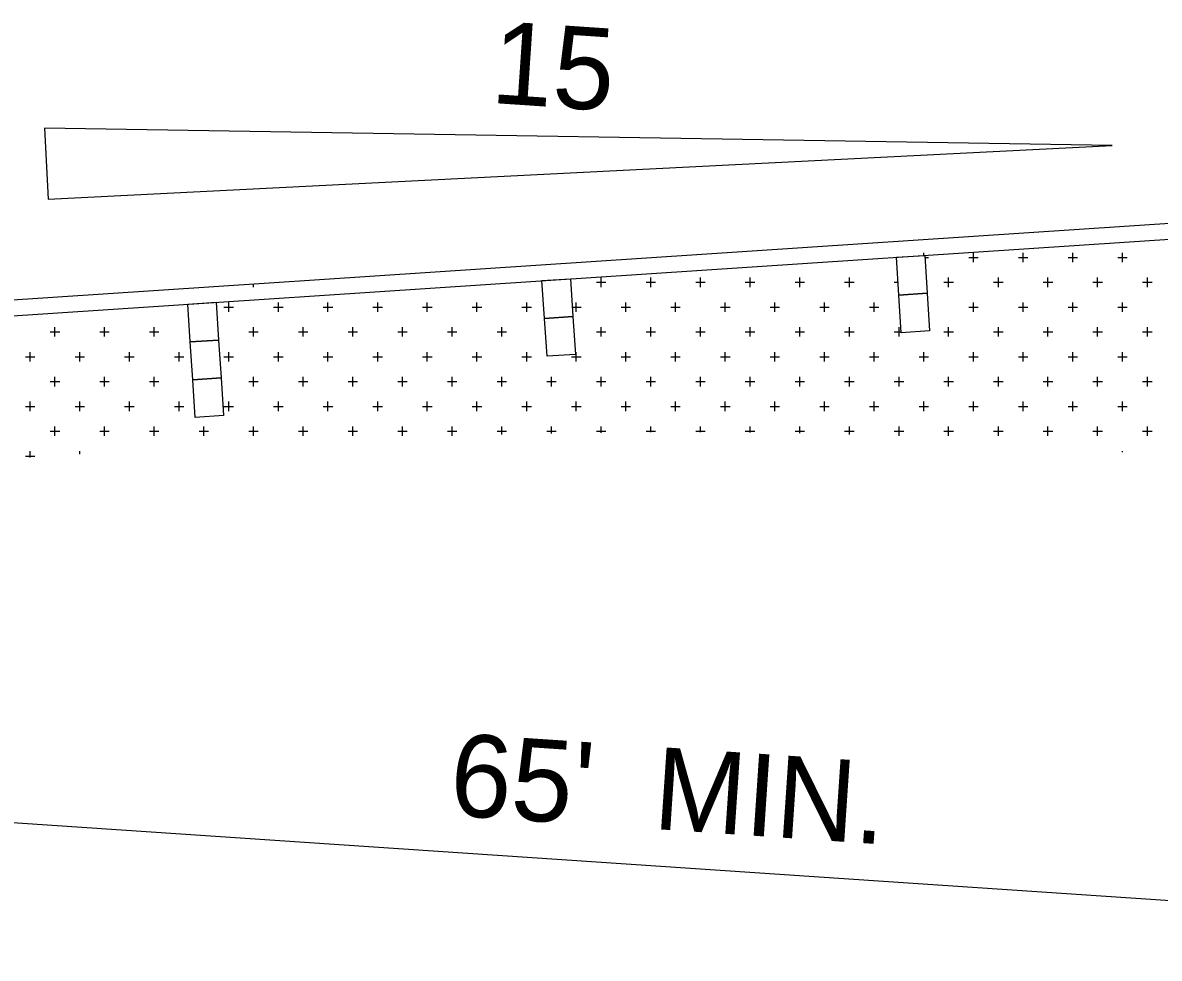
# Model space of a CAD drawing. Extents: x 1312564.5 to 1312581.5, y 1207298.4 to 1207309.4.
# Drawn here: x 1312577.548 to 1312578.654, y 1207304.617 to 1207305.528 of the extents above; entities that cross this region are included whole.
import ezdxf

# ---------------------------------------------------------------- set-up
doc = ezdxf.new("R2010")
doc.units = 0
for name, color, linetype in [('Level 15', 7, 'Continuous'), ('Level 2', 7, 'Continuous'), ('Level 20', 7, 'Continuous'), ('Level 4', 7, 'Continuous')]:
    doc.layers.add(name, color=color, linetype=linetype)

msp = doc.modelspace()

# ---------------------------------------------------------------- linework, layer by layer
at = {"layer": 'Level 15'}
for p, q in [((1312578.6079, 1207305.4083), (1312577.5689, 1207305.4249)), ((1312577.5689, 1207305.4249), (1312577.5724, 1207305.3559)), ((1312577.5724, 1207305.3559), (1312578.6079, 1207305.4083))]:
    msp.add_line(p, q, dxfattribs=at)
msp.add_lwpolyline([(1312576.1506, 1207304.8426), (1312579.498, 1207304.617)], dxfattribs=at)
at = {"layer": 'Level 2'}
for p, q in [((1312579.0887, 1207305.3604), (1312577.009, 1207305.2227)), ((1312577.01, 1207305.2075), (1312579.1015, 1207305.346))]:
    msp.add_line(p, q, dxfattribs=at)
for points in [[(1312578.398, 1207305.2994), (1312578.4256, 1207305.3012), (1312578.428, 1207305.2644), (1312578.4004, 1207305.2626)], [(1312578.0531, 1207305.2766), (1312578.0807, 1207305.2784), (1312578.0831, 1207305.2416), (1312578.0556, 1207305.2398)], [(1312577.7083, 1207305.2537), (1312577.7359, 1207305.2556), (1312577.7383, 1207305.2188), (1312577.7107, 1207305.217)], [(1312578.4004, 1207305.2626), (1312578.428, 1207305.2644), (1312578.4304, 1207305.2277), (1312578.4028, 1207305.2258)], [(1312578.0556, 1207305.2398), (1312578.0831, 1207305.2416), (1312578.0856, 1207305.2048), (1312578.058, 1207305.203)], [(1312577.7107, 1207305.217), (1312577.7383, 1207305.2188), (1312577.7407, 1207305.182), (1312577.7132, 1207305.1802)], [(1312577.7132, 1207305.1802), (1312577.7407, 1207305.182), (1312577.7432, 1207305.1452), (1312577.7156, 1207305.1434)]]:
    msp.add_lwpolyline(points, close=True, dxfattribs=at)
at = {"layer": 'Level 4'}
for p, q in [((1312578.4248, 1207305.3012), (1312578.4248, 1207305.3038)), ((1312578.4257, 1207305.2992), (1312578.4294, 1207305.2992)), ((1312578.4685, 1207305.2992), (1312578.4731, 1207305.2992)), ((1312578.4731, 1207305.2946), (1312578.4731, 1207305.3038)), ((1312578.4731, 1207305.2992), (1312578.4777, 1207305.2992)), ((1312578.5168, 1207305.2992), (1312578.526, 1207305.2992)), ((1312578.5214, 1207305.2946), (1312578.5214, 1207305.3038)), ((1312578.5652, 1207305.2992), (1312578.5744, 1207305.2992)), ((1312578.5698, 1207305.2946), (1312578.5698, 1207305.3038)), ((1312578.6135, 1207305.2992), (1312578.6227, 1207305.2992)), ((1312578.6181, 1207305.2946), (1312578.6181, 1207305.3038)), ((1312578.1107, 1207305.2704), (1312578.1107, 1207305.2796)), ((1312578.159, 1207305.2704), (1312578.159, 1207305.2796)), ((1312578.2073, 1207305.2704), (1312578.2073, 1207305.2796)), ((1312578.2556, 1207305.2704), (1312578.2556, 1207305.2796)), ((1312578.304, 1207305.2704), (1312578.304, 1207305.2796)), ((1312578.3523, 1207305.2704), (1312578.3523, 1207305.2796)), ((1312578.4489, 1207305.2704), (1312578.4489, 1207305.2796)), ((1312578.4973, 1207305.2704), (1312578.4973, 1207305.2796)), ((1312578.5456, 1207305.2704), (1312578.5456, 1207305.2796)), ((1312578.5939, 1207305.2704), (1312578.5939, 1207305.2796)), ((1312578.6423, 1207305.2704), (1312578.6423, 1207305.2796)), ((1312577.7724, 1207305.2704), (1312577.7724, 1207305.2733)), ((1312578.106, 1207305.275), (1312578.1153, 1207305.275)), ((1312578.1544, 1207305.275), (1312578.1636, 1207305.275)), ((1312578.2027, 1207305.275), (1312578.2119, 1207305.275)), ((1312578.251, 1207305.275), (1312578.2602, 1207305.275)), ((1312578.2994, 1207305.275), (1312578.3086, 1207305.275)), ((1312578.3477, 1207305.275), (1312578.3569, 1207305.275)), ((1312578.396, 1207305.275), (1312578.3996, 1207305.275)), ((1312578.4443, 1207305.275), (1312578.4536, 1207305.275)), ((1312578.4927, 1207305.275), (1312578.5019, 1207305.275)), ((1312578.541, 1207305.275), (1312578.5502, 1207305.275)), ((1312578.5893, 1207305.275), (1312578.5985, 1207305.275)), ((1312578.6376, 1207305.275), (1312578.6469, 1207305.275)), ((1312577.7482, 1207305.2508), (1312577.7482, 1207305.2554)), ((1312577.7965, 1207305.2508), (1312577.7965, 1207305.2554)), ((1312577.8448, 1207305.2508), (1312577.8448, 1207305.2554)), ((1312577.8932, 1207305.2508), (1312577.8932, 1207305.2554)), ((1312577.9415, 1207305.2508), (1312577.9415, 1207305.2554)), ((1312577.9898, 1207305.2508), (1312577.9898, 1207305.2554)), ((1312578.0382, 1207305.2508), (1312578.0382, 1207305.2554)), ((1312578.0865, 1207305.2508), (1312578.0865, 1207305.2554)), ((1312578.1348, 1207305.2508), (1312578.1348, 1207305.2554)), ((1312578.1831, 1207305.2508), (1312578.1831, 1207305.2554)), ((1312578.2315, 1207305.2508), (1312578.2315, 1207305.2554)), ((1312578.2798, 1207305.2508), (1312578.2798, 1207305.2554)), ((1312578.3281, 1207305.2508), (1312578.3281, 1207305.2554)), ((1312578.3765, 1207305.2508), (1312578.3765, 1207305.2554)), ((1312578.4731, 1207305.2508), (1312578.4731, 1207305.2554)), ((1312578.5214, 1207305.2508), (1312578.5214, 1207305.2554)), ((1312578.5698, 1207305.2508), (1312578.5698, 1207305.2554)), ((1312578.6181, 1207305.2508), (1312578.6181, 1207305.2554)), ((1312577.7436, 1207305.2508), (1312577.7528, 1207305.2508)), ((1312577.7482, 1207305.2462), (1312577.7482, 1207305.2508)), ((1312577.7919, 1207305.2508), (1312577.8011, 1207305.2508)), ((1312577.7965, 1207305.2462), (1312577.7965, 1207305.2508)), ((1312577.8402, 1207305.2508), (1312577.8495, 1207305.2508)), ((1312577.8448, 1207305.2462), (1312577.8448, 1207305.2508)), ((1312577.8886, 1207305.2508), (1312577.8932, 1207305.2508)), ((1312577.8932, 1207305.2462), (1312577.8932, 1207305.2508)), ((1312577.8932, 1207305.2508), (1312577.8978, 1207305.2508)), ((1312577.9369, 1207305.2508), (1312577.9461, 1207305.2508)), ((1312577.9415, 1207305.2462), (1312577.9415, 1207305.2508)), ((1312577.9852, 1207305.2508), (1312577.9944, 1207305.2508)), ((1312577.9898, 1207305.2462), (1312577.9898, 1207305.2508)), ((1312578.0336, 1207305.2508), (1312578.0428, 1207305.2508)), ((1312578.0382, 1207305.2462), (1312578.0382, 1207305.2508)), ((1312578.0825, 1207305.2508), (1312578.0911, 1207305.2508)), ((1312578.0865, 1207305.2462), (1312578.0865, 1207305.2508)), ((1312578.1302, 1207305.2508), (1312578.1394, 1207305.2508)), ((1312578.1348, 1207305.2462), (1312578.1348, 1207305.2508)), ((1312578.1785, 1207305.2508), (1312578.1831, 1207305.2508)), ((1312578.1831, 1207305.2462), (1312578.1831, 1207305.2508)), ((1312578.1831, 1207305.2508), (1312578.1877, 1207305.2508)), ((1312578.2269, 1207305.2508), (1312578.2361, 1207305.2508)), ((1312578.2315, 1207305.2462), (1312578.2315, 1207305.2508)), ((1312578.2752, 1207305.2508), (1312578.2844, 1207305.2508)), ((1312578.2798, 1207305.2462), (1312578.2798, 1207305.2508)), ((1312578.3235, 1207305.2508), (1312578.3327, 1207305.2508)), ((1312578.3281, 1207305.2462), (1312578.3281, 1207305.2508)), ((1312578.3718, 1207305.2508), (1312578.3811, 1207305.2508)), ((1312578.3765, 1207305.2462), (1312578.3765, 1207305.2508)), ((1312578.4289, 1207305.2508), (1312578.4294, 1207305.2508)), ((1312578.4685, 1207305.2508), (1312578.4731, 1207305.2508)), ((1312578.4731, 1207305.2462), (1312578.4731, 1207305.2508)), ((1312578.4731, 1207305.2508), (1312578.4777, 1207305.2508)), ((1312578.5168, 1207305.2508), (1312578.526, 1207305.2508)), ((1312578.5214, 1207305.2462), (1312578.5214, 1207305.2508)), ((1312578.5652, 1207305.2508), (1312578.5744, 1207305.2508)), ((1312578.5698, 1207305.2462), (1312578.5698, 1207305.2508)), ((1312578.6135, 1207305.2508), (1312578.6227, 1207305.2508)), ((1312578.6181, 1207305.2462), (1312578.6181, 1207305.2508)), ((1312577.5744, 1207305.2267), (1312577.5837, 1207305.2267)), ((1312577.579, 1207305.2221), (1312577.579, 1207305.2313)), ((1312577.6228, 1207305.2267), (1312577.632, 1207305.2267)), ((1312577.6274, 1207305.2221), (1312577.6274, 1207305.2313)), ((1312577.6711, 1207305.2267), (1312577.6803, 1207305.2267)), ((1312577.6757, 1207305.2221), (1312577.6757, 1207305.2313)), ((1312577.7677, 1207305.2267), (1312577.777, 1207305.2267)), ((1312577.7724, 1207305.2221), (1312577.7724, 1207305.2313)), ((1312577.8161, 1207305.2267), (1312577.8253, 1207305.2267)), ((1312577.8207, 1207305.2221), (1312577.8207, 1207305.2313)), ((1312577.8644, 1207305.2267), (1312577.8736, 1207305.2267)), ((1312577.869, 1207305.2221), (1312577.869, 1207305.2313)), ((1312577.9127, 1207305.2267), (1312577.9219, 1207305.2267)), ((1312577.9173, 1207305.2221), (1312577.9173, 1207305.2313)), ((1312577.9611, 1207305.2267), (1312577.9703, 1207305.2267)), ((1312577.9657, 1207305.2221), (1312577.9657, 1207305.2313)), ((1312578.0094, 1207305.2267), (1312578.0186, 1207305.2267)), ((1312578.014, 1207305.2221), (1312578.014, 1207305.2313)), ((1312578.106, 1207305.2267), (1312578.1153, 1207305.2267)), ((1312578.1107, 1207305.2221), (1312578.1107, 1207305.2313)), ((1312578.1544, 1207305.2267), (1312578.1636, 1207305.2267)), ((1312578.159, 1207305.2221), (1312578.159, 1207305.2313)), ((1312578.2027, 1207305.2267), (1312578.2119, 1207305.2267)), ((1312578.2073, 1207305.2221), (1312578.2073, 1207305.2313)), ((1312578.251, 1207305.2267), (1312578.2602, 1207305.2267)), ((1312578.2556, 1207305.2221), (1312578.2556, 1207305.2313)), ((1312578.2994, 1207305.2267), (1312578.3086, 1207305.2267)), ((1312578.304, 1207305.2221), (1312578.304, 1207305.2313)), ((1312578.3477, 1207305.2267), (1312578.3569, 1207305.2267)), ((1312578.3523, 1207305.2221), (1312578.3523, 1207305.2313)), ((1312578.396, 1207305.2267), (1312578.4028, 1207305.2267)), ((1312578.4006, 1207305.2221), (1312578.4006, 1207305.2313)), ((1312578.4443, 1207305.2267), (1312578.4536, 1207305.2267)), ((1312578.4489, 1207305.2221), (1312578.4489, 1207305.2313)), ((1312578.4927, 1207305.2267), (1312578.5019, 1207305.2267)), ((1312578.4973, 1207305.2221), (1312578.4973, 1207305.2313)), ((1312578.541, 1207305.2267), (1312578.5502, 1207305.2267)), ((1312578.5456, 1207305.2221), (1312578.5456, 1207305.2313)), ((1312578.5893, 1207305.2267), (1312578.5985, 1207305.2267)), ((1312578.5939, 1207305.2221), (1312578.5939, 1207305.2313)), ((1312578.6376, 1207305.2267), (1312578.6469, 1207305.2267)), ((1312578.6423, 1207305.2221), (1312578.6423, 1207305.2313)), ((1312577.5503, 1207305.2025), (1312577.5595, 1207305.2025)), ((1312577.5549, 1207305.1979), (1312577.5549, 1207305.2071)), ((1312577.5986, 1207305.2025), (1312577.6032, 1207305.2025)), ((1312577.6032, 1207305.1979), (1312577.6032, 1207305.2071)), ((1312577.6032, 1207305.2025), (1312577.6078, 1207305.2025)), ((1312577.6469, 1207305.2025), (1312577.6561, 1207305.2025)), ((1312577.6515, 1207305.1979), (1312577.6515, 1207305.2071)), ((1312577.6953, 1207305.2025), (1312577.7045, 1207305.2025)), ((1312577.6999, 1207305.1979), (1312577.6999, 1207305.2071)), ((1312577.7436, 1207305.2025), (1312577.7528, 1207305.2025)), ((1312577.7482, 1207305.1979), (1312577.7482, 1207305.2071)), ((1312577.7919, 1207305.2025), (1312577.8011, 1207305.2025)), ((1312577.7965, 1207305.1979), (1312577.7965, 1207305.2071)), ((1312577.8402, 1207305.2025), (1312577.8495, 1207305.2025)), ((1312577.8448, 1207305.1979), (1312577.8448, 1207305.2071)), ((1312577.8886, 1207305.2025), (1312577.8932, 1207305.2025)), ((1312577.8932, 1207305.1979), (1312577.8932, 1207305.2071)), ((1312577.8932, 1207305.2025), (1312577.8978, 1207305.2025)), ((1312577.9369, 1207305.2025), (1312577.9461, 1207305.2025)), ((1312577.9415, 1207305.1979), (1312577.9415, 1207305.2071)), ((1312577.9852, 1207305.2025), (1312577.9944, 1207305.2025)), ((1312577.9898, 1207305.1979), (1312577.9898, 1207305.2071)), ((1312578.0336, 1207305.2025), (1312578.0428, 1207305.2025)), ((1312578.0382, 1207305.1979), (1312578.0382, 1207305.2071)), ((1312578.0819, 1207305.2025), (1312578.0911, 1207305.2025)), ((1312578.0865, 1207305.1979), (1312578.0865, 1207305.2071)), ((1312578.1302, 1207305.2025), (1312578.1394, 1207305.2025)), ((1312578.1348, 1207305.1979), (1312578.1348, 1207305.2071)), ((1312578.1785, 1207305.2025), (1312578.1831, 1207305.2025)), ((1312578.1831, 1207305.1979), (1312578.1831, 1207305.2071)), ((1312578.1831, 1207305.2025), (1312578.1877, 1207305.2025)), ((1312578.2269, 1207305.2025), (1312578.2361, 1207305.2025)), ((1312578.2315, 1207305.1979), (1312578.2315, 1207305.2071)), ((1312578.2752, 1207305.2025), (1312578.2844, 1207305.2025)), ((1312578.2798, 1207305.1979), (1312578.2798, 1207305.2071)), ((1312578.3235, 1207305.2025), (1312578.3327, 1207305.2025)), ((1312578.3281, 1207305.1979), (1312578.3281, 1207305.2071)), ((1312578.3718, 1207305.2025), (1312578.3811, 1207305.2025)), ((1312578.3765, 1207305.1979), (1312578.3765, 1207305.2071)), ((1312578.4202, 1207305.2025), (1312578.4294, 1207305.2025)), ((1312578.4248, 1207305.1979), (1312578.4248, 1207305.2071)), ((1312578.4685, 1207305.2025), (1312578.4731, 1207305.2025)), ((1312578.4731, 1207305.1979), (1312578.4731, 1207305.2071)), ((1312578.4731, 1207305.2025), (1312578.4777, 1207305.2025)), ((1312578.5168, 1207305.2025), (1312578.526, 1207305.2025)), ((1312578.5214, 1207305.1979), (1312578.5214, 1207305.2071)), ((1312578.5652, 1207305.2025), (1312578.5744, 1207305.2025)), ((1312578.5698, 1207305.1979), (1312578.5698, 1207305.2071)), ((1312578.6135, 1207305.2025), (1312578.6227, 1207305.2025)), ((1312578.6181, 1207305.1979), (1312578.6181, 1207305.2071)), ((1312577.5744, 1207305.1783), (1312577.5837, 1207305.1783)), ((1312577.579, 1207305.1737), (1312577.579, 1207305.183)), ((1312577.6228, 1207305.1783), (1312577.632, 1207305.1783)), ((1312577.6274, 1207305.1737), (1312577.6274, 1207305.183)), ((1312577.6711, 1207305.1783), (1312577.6803, 1207305.1783)), ((1312577.6757, 1207305.1737), (1312577.6757, 1207305.183)), ((1312577.7677, 1207305.1783), (1312577.777, 1207305.1783)), ((1312577.7724, 1207305.1737), (1312577.7724, 1207305.183)), ((1312577.8161, 1207305.1783), (1312577.8253, 1207305.1783)), ((1312577.8207, 1207305.1737), (1312577.8207, 1207305.183)), ((1312577.8644, 1207305.1783), (1312577.8736, 1207305.1783)), ((1312577.869, 1207305.1737), (1312577.869, 1207305.183)), ((1312577.9127, 1207305.1783), (1312577.9219, 1207305.1783)), ((1312577.9173, 1207305.1737), (1312577.9173, 1207305.183)), ((1312577.9611, 1207305.1783), (1312577.9703, 1207305.1783)), ((1312577.9657, 1207305.1737), (1312577.9657, 1207305.183)), ((1312578.0094, 1207305.1783), (1312578.0186, 1207305.1783)), ((1312578.014, 1207305.1737), (1312578.014, 1207305.183)), ((1312578.0577, 1207305.1783), (1312578.0669, 1207305.1783)), ((1312578.0623, 1207305.1737), (1312578.0623, 1207305.183)), ((1312578.106, 1207305.1783), (1312578.1153, 1207305.1783)), ((1312578.1107, 1207305.1737), (1312578.1107, 1207305.183)), ((1312578.1544, 1207305.1783), (1312578.1636, 1207305.1783)), ((1312578.159, 1207305.1737), (1312578.159, 1207305.183)), ((1312578.2027, 1207305.1783), (1312578.2119, 1207305.1783)), ((1312578.2073, 1207305.1737), (1312578.2073, 1207305.183)), ((1312578.251, 1207305.1783), (1312578.2602, 1207305.1783)), ((1312578.2556, 1207305.1737), (1312578.2556, 1207305.183)), ((1312578.2994, 1207305.1783), (1312578.3086, 1207305.1783)), ((1312578.304, 1207305.1737), (1312578.304, 1207305.183)), ((1312578.3477, 1207305.1783), (1312578.3569, 1207305.1783)), ((1312578.3523, 1207305.1737), (1312578.3523, 1207305.183)), ((1312578.396, 1207305.1783), (1312578.4052, 1207305.1783)), ((1312578.4006, 1207305.1737), (1312578.4006, 1207305.183)), ((1312578.4443, 1207305.1783), (1312578.4536, 1207305.1783)), ((1312578.4489, 1207305.1737), (1312578.4489, 1207305.183)), ((1312578.4927, 1207305.1783), (1312578.5019, 1207305.1783)), ((1312578.4973, 1207305.1737), (1312578.4973, 1207305.183)), ((1312578.541, 1207305.1783), (1312578.5502, 1207305.1783)), ((1312578.5456, 1207305.1737), (1312578.5456, 1207305.183)), ((1312578.5893, 1207305.1783), (1312578.5985, 1207305.1783)), ((1312578.5939, 1207305.1737), (1312578.5939, 1207305.183)), ((1312578.6376, 1207305.1783), (1312578.6469, 1207305.1783)), ((1312578.6423, 1207305.1737), (1312578.6423, 1207305.183)), ((1312577.5503, 1207305.1542), (1312577.5595, 1207305.1542)), ((1312577.5549, 1207305.1496), (1312577.5549, 1207305.1588)), ((1312577.5986, 1207305.1542), (1312577.6032, 1207305.1542)), ((1312577.6032, 1207305.1496), (1312577.6032, 1207305.1588)), ((1312577.6032, 1207305.1542), (1312577.6078, 1207305.1542)), ((1312577.6469, 1207305.1542), (1312577.6561, 1207305.1542)), ((1312577.6515, 1207305.1496), (1312577.6515, 1207305.1588)), ((1312577.6953, 1207305.1542), (1312577.7045, 1207305.1542)), ((1312577.6999, 1207305.1496), (1312577.6999, 1207305.1588)), ((1312577.7436, 1207305.1542), (1312577.7528, 1207305.1542)), ((1312577.7482, 1207305.1496), (1312577.7482, 1207305.1588)), ((1312577.7919, 1207305.1542), (1312577.8011, 1207305.1542)), ((1312577.7965, 1207305.1496), (1312577.7965, 1207305.1588)), ((1312577.8402, 1207305.1542), (1312577.8495, 1207305.1542)), ((1312577.8448, 1207305.1496), (1312577.8448, 1207305.1588)), ((1312577.8886, 1207305.1542), (1312577.8932, 1207305.1542)), ((1312577.8932, 1207305.1496), (1312577.8932, 1207305.1588)), ((1312577.8932, 1207305.1542), (1312577.8978, 1207305.1542)), ((1312577.9369, 1207305.1542), (1312577.9461, 1207305.1542)), ((1312577.9415, 1207305.1496), (1312577.9415, 1207305.1588)), ((1312577.9852, 1207305.1542), (1312577.9944, 1207305.1542)), ((1312577.9898, 1207305.1496), (1312577.9898, 1207305.1588)), ((1312578.0336, 1207305.1542), (1312578.0428, 1207305.1542)), ((1312578.0382, 1207305.1496), (1312578.0382, 1207305.1588)), ((1312578.0819, 1207305.1542), (1312578.0911, 1207305.1542)), ((1312578.0865, 1207305.1496), (1312578.0865, 1207305.1588)), ((1312578.1302, 1207305.1542), (1312578.1394, 1207305.1542)), ((1312578.1348, 1207305.1496), (1312578.1348, 1207305.1588)), ((1312578.1785, 1207305.1542), (1312578.1831, 1207305.1542)), ((1312578.1831, 1207305.1496), (1312578.1831, 1207305.1588)), ((1312578.1831, 1207305.1542), (1312578.1877, 1207305.1542)), ((1312578.2269, 1207305.1542), (1312578.2361, 1207305.1542)), ((1312578.2315, 1207305.1496), (1312578.2315, 1207305.1588)), ((1312578.2752, 1207305.1542), (1312578.2844, 1207305.1542)), ((1312578.2798, 1207305.1496), (1312578.2798, 1207305.1588)), ((1312578.3235, 1207305.1542), (1312578.3327, 1207305.1542)), ((1312578.3281, 1207305.1496), (1312578.3281, 1207305.1588)), ((1312578.3718, 1207305.1542), (1312578.3811, 1207305.1542)), ((1312578.3765, 1207305.1496), (1312578.3765, 1207305.1588)), ((1312578.4202, 1207305.1542), (1312578.4294, 1207305.1542)), ((1312578.4248, 1207305.1496), (1312578.4248, 1207305.1588)), ((1312578.4685, 1207305.1542), (1312578.4731, 1207305.1542)), ((1312578.4731, 1207305.1496), (1312578.4731, 1207305.1588)), ((1312578.4731, 1207305.1542), (1312578.4777, 1207305.1542)), ((1312578.5168, 1207305.1542), (1312578.526, 1207305.1542)), ((1312578.5214, 1207305.1496), (1312578.5214, 1207305.1588)), ((1312578.5652, 1207305.1542), (1312578.5744, 1207305.1542)), ((1312578.5698, 1207305.1496), (1312578.5698, 1207305.1588)), ((1312578.6135, 1207305.1542), (1312578.6227, 1207305.1542)), ((1312578.6181, 1207305.1496), (1312578.6181, 1207305.1588)), ((1312577.579, 1207305.1254), (1312577.579, 1207305.1346)), ((1312577.6274, 1207305.1254), (1312577.6274, 1207305.1346)), ((1312577.6757, 1207305.1254), (1312577.6757, 1207305.1346)), ((1312577.724, 1207305.1254), (1312577.724, 1207305.1346)), ((1312577.7724, 1207305.1254), (1312577.7724, 1207305.1346)), ((1312577.8207, 1207305.1254), (1312577.8207, 1207305.1346)), ((1312577.869, 1207305.1254), (1312577.869, 1207305.1346)), ((1312577.9173, 1207305.1254), (1312577.9173, 1207305.1346)), ((1312577.9657, 1207305.1254), (1312577.9657, 1207305.1346)), ((1312578.014, 1207305.1267), (1312578.014, 1207305.1346)), ((1312578.0623, 1207305.1278), (1312578.0623, 1207305.1346)), ((1312578.1107, 1207305.1286), (1312578.1107, 1207305.1346)), ((1312578.159, 1207305.1291), (1312578.159, 1207305.1346)), ((1312578.2073, 1207305.1292), (1312578.2073, 1207305.1346)), ((1312578.2556, 1207305.1289), (1312578.2556, 1207305.1346)), ((1312578.304, 1207305.1281), (1312578.304, 1207305.1346)), ((1312578.3523, 1207305.1267), (1312578.3523, 1207305.1346)), ((1312578.4006, 1207305.1254), (1312578.4006, 1207305.1346)), ((1312578.4489, 1207305.1254), (1312578.4489, 1207305.1346)), ((1312578.4973, 1207305.1254), (1312578.4973, 1207305.1346)), ((1312578.5456, 1207305.1254), (1312578.5456, 1207305.1346)), ((1312578.5939, 1207305.1254), (1312578.5939, 1207305.1346)), ((1312578.6423, 1207305.1254), (1312578.6423, 1207305.1346)), ((1312577.5744, 1207305.13), (1312577.5837, 1207305.13)), ((1312577.6228, 1207305.13), (1312577.632, 1207305.13)), ((1312577.6711, 1207305.13), (1312577.6803, 1207305.13)), ((1312577.7194, 1207305.13), (1312577.7286, 1207305.13)), ((1312577.7677, 1207305.13), (1312577.777, 1207305.13)), ((1312577.8161, 1207305.13), (1312577.8253, 1207305.13)), ((1312577.8644, 1207305.13), (1312577.8736, 1207305.13)), ((1312577.9127, 1207305.13), (1312577.9219, 1207305.13)), ((1312577.9611, 1207305.13), (1312577.9703, 1207305.13)), ((1312578.0094, 1207305.13), (1312578.0186, 1207305.13)), ((1312578.0577, 1207305.13), (1312578.0669, 1207305.13)), ((1312578.106, 1207305.13), (1312578.1153, 1207305.13)), ((1312578.1544, 1207305.13), (1312578.1636, 1207305.13)), ((1312578.2027, 1207305.13), (1312578.2119, 1207305.13)), ((1312578.251, 1207305.13), (1312578.2602, 1207305.13)), ((1312578.2994, 1207305.13), (1312578.3086, 1207305.13)), ((1312578.3477, 1207305.13), (1312578.3569, 1207305.13)), ((1312578.396, 1207305.13), (1312578.4052, 1207305.13)), ((1312578.4443, 1207305.13), (1312578.4536, 1207305.13)), ((1312578.4927, 1207305.13), (1312578.5019, 1207305.13)), ((1312578.541, 1207305.13), (1312578.5502, 1207305.13)), ((1312578.5893, 1207305.13), (1312578.5985, 1207305.13)), ((1312578.6376, 1207305.13), (1312578.6469, 1207305.13)), ((1312577.5549, 1207305.1043), (1312577.5549, 1207305.1105)), ((1312577.6032, 1207305.1077), (1312577.6032, 1207305.1105)), ((1312578.6181, 1207305.1096), (1312578.6181, 1207305.1105)), ((1312577.5503, 1207305.1059), (1312577.5595, 1207305.1059))]:
    msp.add_line(p, q, dxfattribs=at)

# ---------------------------------------------------------------- texts
at = {"layer": 'Level 15'}
msp.add_text('15', height=0.08, rotation=356.1437, dxfattribs=at).set_placement((1312578.0024, 1207305.4497))
at = {"layer": 'Level 20'}
msp.add_text("65'  MIN.", height=0.08, rotation=356.1437, dxfattribs=at).set_placement((1312577.9619, 1207304.7563))

doc.saveas('drawing.dxf')
